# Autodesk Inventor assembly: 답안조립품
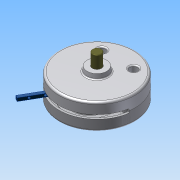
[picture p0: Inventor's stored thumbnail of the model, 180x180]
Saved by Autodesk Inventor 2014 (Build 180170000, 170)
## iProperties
Created: 2015-06
Part Number: 답안조립품
Document SubType Name: Assembly
Designer: Administrator
Author: Administrator
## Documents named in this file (10)
- C:\Documents and Settings\Administrator\바탕 화면\450631V1025\답안조립품.iam
- C:\Documents and Settings\Administrator\바탕 화면\450631V1025\1-본체.ipt
- C:\Documents and Settings\Administrator\바탕 화면\450631V1025\베어링62_22.ipt
- C:\Documents and Settings\Administrator\바탕 화면\450631V1025\덮개.ipt
- C:\Documents and Settings\Administrator\바탕 화면\450631V1025\축.ipt
- C:\Documents and Settings\Administrator\바탕 화면\450631V1025\멈춤링.ipt
- C:\Documents and Settings\Administrator\바탕 화면\450631V1025\슬라이더.ipt
- C:\Documents and Settings\Administrator\바탕 화면\450631V1025\평행핀.ipt
- C:\Documents and Settings\Administrator\바탕 화면\450631V1025\슬라이더2.ipt
- C:\Documents and Settings\Administrator\바탕 화면\450631V1025\M10x35.ipt
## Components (8 placed, 5 different names)
1. 1-본체:1
2. KS B 2023 62/22 - 22 x 50 x 14:1
3. KS B 2023 62/22 - 22 x 50 x 14:2
4. KS B 1336 22 x 1.2:1
5. KS B 1336 22 x 1.2:2
6. KS B 1320 B B 5 x  20:1
7. KS B 1003 - 미터 M 10 x 35:1
8. KS B 1003 - 미터 M 10 x 35:2
